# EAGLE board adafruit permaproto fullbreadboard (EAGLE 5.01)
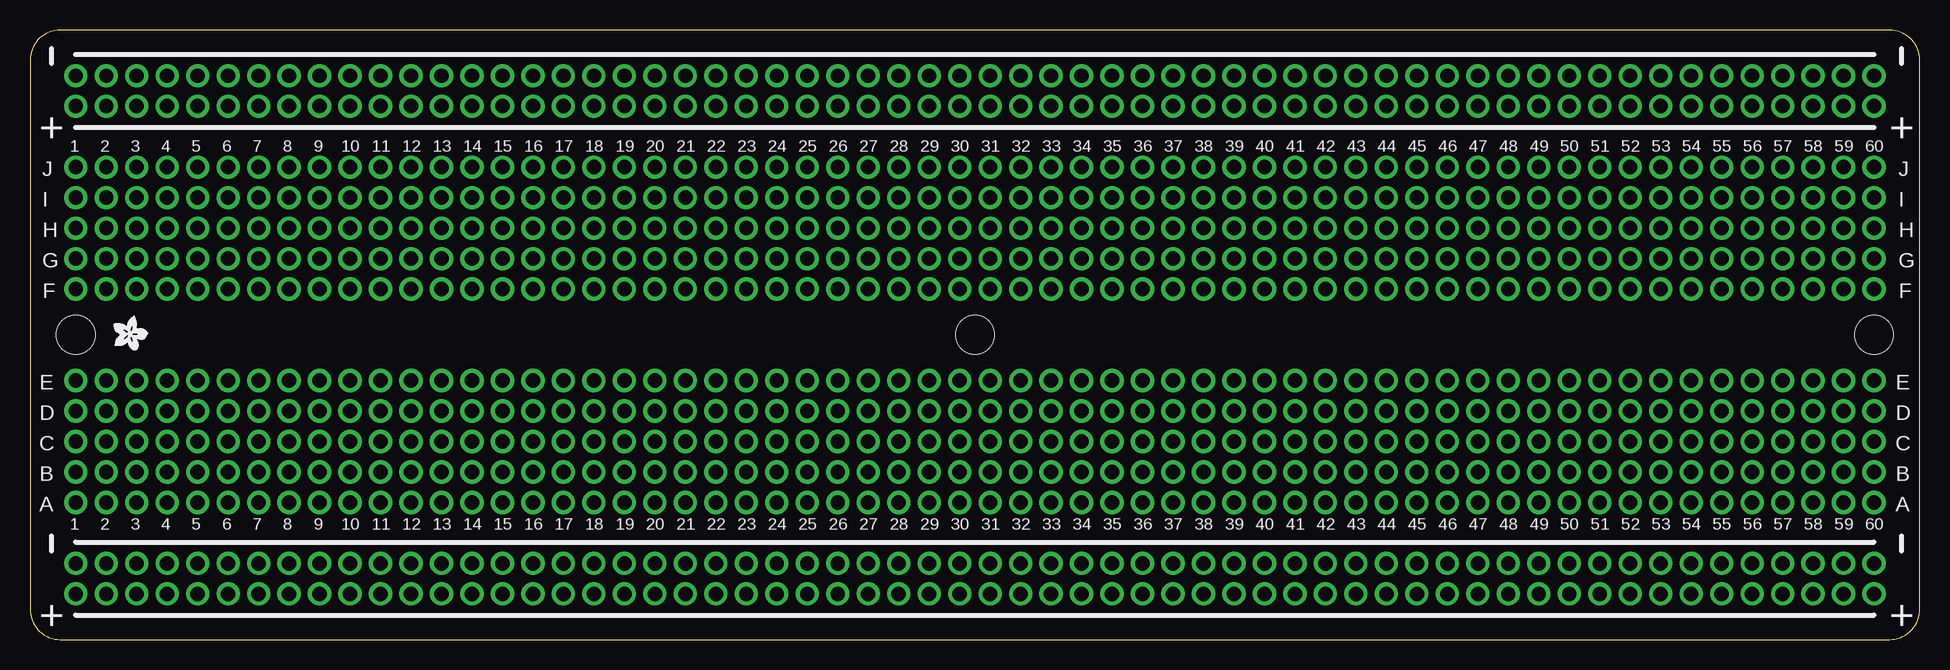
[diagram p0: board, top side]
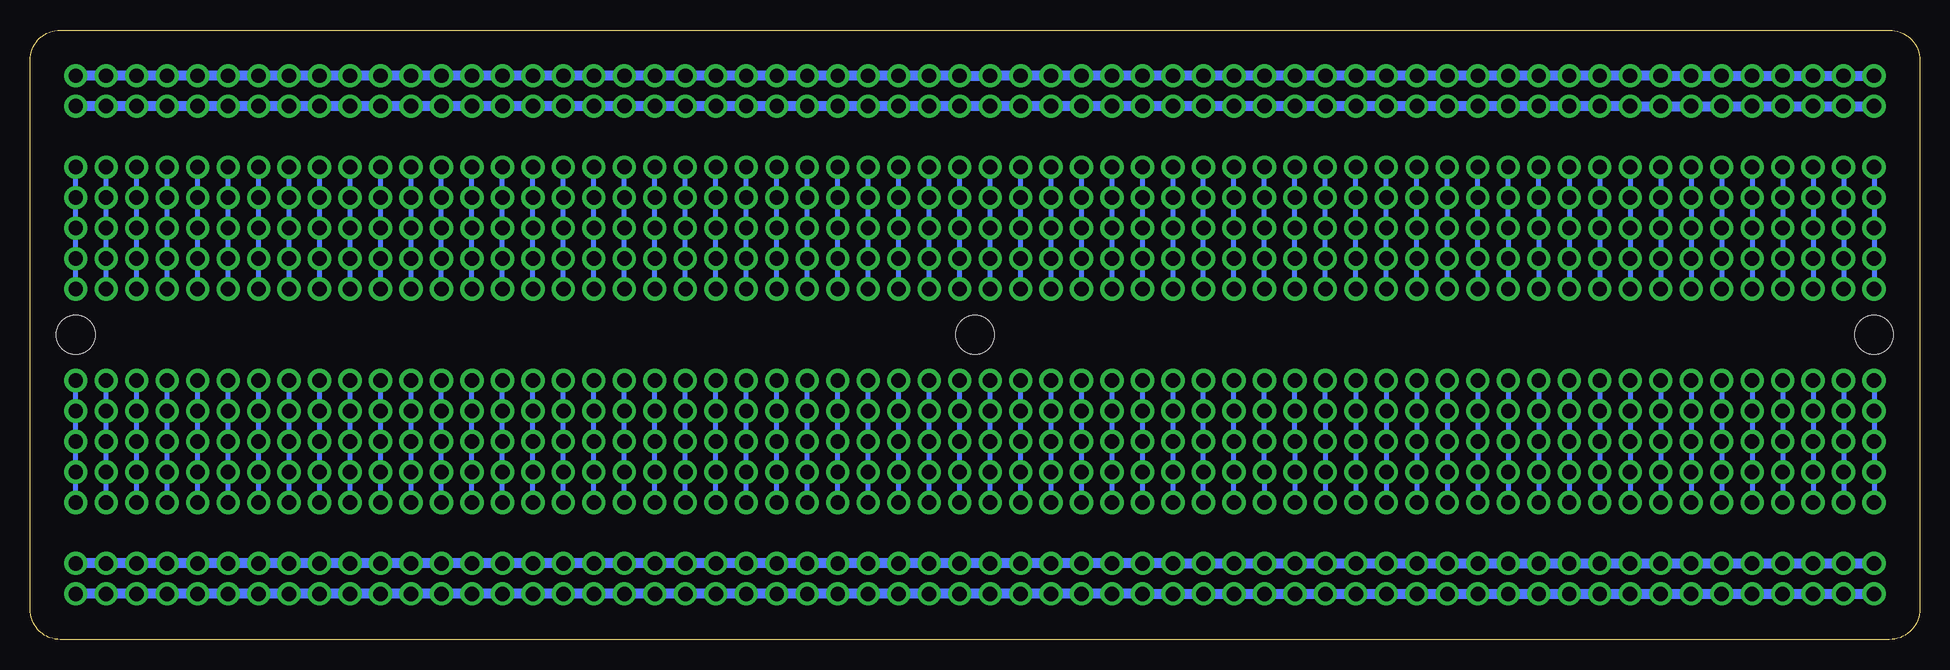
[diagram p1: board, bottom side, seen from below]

Size 157.48 x 50.8 mm. Coordinates in mm from the lower left corner, seen from the top.
Outline: 2.54,50.8 arc90 0,48.26 0,2.54 arc90 2.54,0 154.94,0 arc90 157.48,2.54 157.48,48.26 arc90 154.94,50.8 2.54,50.8
Copper layers (1*16): Top 0.035mm / dielectric 1.5mm / Bottom 0.035mm
Design rules "default": minimum track width 10mil, minimum drill 24mil, track to track 8mil, track to pad 8mil, pad to pad 8mil, via to via 8mil, smd to smd 8mil, copper to edge 40mil, drill to drill 8mil, minimum pad ring 10mil, minimum via ring 8mil, stop-mask expansion 4mil, vias tented up to drill 0mil, thermal gap 10mil
Holes 3.2 mm at 3.81,25.4 153.67,25.4 78.74,25.4

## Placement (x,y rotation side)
U$1  [ADAFRUIT200MIL]  8.38,25.65 270 top

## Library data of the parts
U$1 = adafruit

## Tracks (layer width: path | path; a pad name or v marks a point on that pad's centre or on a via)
N$1  (via drill 1.2 pad 1.93)
  Bottom 0.406: v3.81,21.59 v3.81,19.05 v3.81,16.51 v3.81,13.97 v3.81,11.43
N$2  (via drill 1.2 pad 1.93)
  Bottom 0.406: v6.35,11.43 v6.35,13.97 v6.35,16.51 v6.35,19.05 v6.35,21.59
N$3  (via drill 1.2 pad 1.93)
  Bottom 0.406: v8.89,21.59 v8.89,19.05 v8.89,16.51 v8.89,13.97 v8.89,11.43
N$4  (via drill 1.2 pad 1.93)
  Bottom 0.406: v11.43,11.43 v11.43,13.97 v11.43,16.51 v11.43,19.05 v11.43,21.59
N$5  (via drill 1.2 pad 1.93)
  Bottom 0.406: v13.97,21.59 v13.97,19.05 v13.97,16.51 v13.97,13.97 v13.97,11.43
N$6  (via drill 1.2 pad 1.93)
  Bottom 0.406: v16.51,11.43 v16.51,13.97 v16.51,16.51 v16.51,19.05 v16.51,21.59
N$7  (via drill 1.2 pad 1.93)
  Bottom 0.406: v21.59,11.43 v21.59,13.97 v21.59,16.51 v21.59,19.05 v21.59,21.59
N$8  (via drill 1.2 pad 1.93)
  Bottom 0.406: v19.05,21.59 v19.05,19.05 v19.05,16.51 v19.05,13.97 v19.05,11.43
N$9  (via drill 1.2 pad 1.93)
  Bottom 0.406: v24.13,21.59 v24.13,19.05 v24.13,16.51 v24.13,13.97 v24.13,11.43
N$10  (via drill 1.2 pad 1.93)
  Bottom 0.406: v26.67,21.59 v26.67,19.05 v26.67,16.51 v26.67,13.97 v26.67,11.43
N$11  (via drill 1.2 pad 1.93)
  Bottom 0.406: v29.21,21.59 v29.21,19.05 v29.21,16.51 v29.21,13.97 v29.21,11.43
N$12  (via drill 1.2 pad 1.93)
  Bottom 0.406: v31.75,11.43 v31.75,13.97 v31.75,16.51 v31.75,19.05 v31.75,21.59
N$13  (via drill 1.2 pad 1.93)
  Bottom 0.406: v34.29,21.59 v34.29,19.05 v34.29,16.51 v34.29,13.97 v34.29,11.43
N$14  (via drill 1.2 pad 1.93)
  Bottom 0.406: v36.83,11.43 v36.83,13.97 v36.83,16.51 v36.83,19.05 v36.83,21.59
N$15  (via drill 1.2 pad 1.93)
  Bottom 0.406: v39.37,11.43 v39.37,13.97 v39.37,16.51 | v39.37,19.05 v39.37,16.51 | v39.37,21.59 v39.37,19.05 | v39.37,19.05 v39.37,16.51
N$16  (via drill 1.2 pad 1.93)
  Bottom 0.406: v41.91,21.59 v41.91,19.05 v41.91,16.51 v41.91,13.97 v41.91,11.43
N$17  (via drill 1.2 pad 1.93)
  Bottom 0.406: v46.99,21.59 v46.99,19.05 v46.99,16.51 v46.99,13.97 v46.99,11.43
N$18  (via drill 1.2 pad 1.93)
  Bottom 0.406: v44.45,11.43 v44.45,13.97 v44.45,16.51 v44.45,19.05 v44.45,21.59
N$19  (via drill 1.2 pad 1.93)
  Bottom 0.406: v49.53,21.59 v49.53,19.05 v49.53,16.51 v49.53,13.97 v49.53,11.43
N$20  (via drill 1.2 pad 1.93)
  Bottom 0.406: v52.07,11.43 v52.07,13.97 v52.07,16.51 v52.07,19.05 v52.07,21.59
N$21  (via drill 1.2 pad 1.93)
  Bottom 0.406: v57.15,11.43 v57.15,13.97 v57.15,16.51 v57.15,19.05 v57.15,21.59
N$22  (via drill 1.2 pad 1.93)
  Bottom 0.406: v54.61,21.59 v54.61,19.05 v54.61,16.51 v54.61,13.97 v54.61,11.43
N$23  (via drill 1.2 pad 1.93)
  Bottom 0.406: v59.69,21.59 v59.69,19.05 v59.69,16.51 v59.69,13.97 v59.69,11.43
N$24  (via drill 1.2 pad 1.93)
  Bottom 0.406: v62.23,11.43 v62.23,13.97 v62.23,16.51 v62.23,19.05 v62.23,21.59
N$25  (via drill 1.2 pad 1.93)
  Bottom 0.406: v64.77,21.59 v64.77,19.05 v64.77,16.51 v64.77,13.97 v64.77,11.43
N$26  (via drill 1.2 pad 1.93)
  Bottom 0.406: v67.31,11.43 v67.31,13.97 v67.31,16.51 v67.31,19.05 v67.31,21.59
N$27  (via drill 1.2 pad 1.93)
  Bottom 0.406: v72.39,21.59 v72.39,19.05 v72.39,16.51 v72.39,13.97 v72.39,11.43
N$28  (via drill 1.2 pad 1.93)
  Bottom 0.406: v69.85,11.43 v69.85,13.97 v69.85,16.51 v69.85,19.05 v69.85,21.59
N$29  (via drill 1.2 pad 1.93)
  Bottom 0.406: v74.93,21.59 v74.93,19.05 v74.93,16.51 v74.93,13.97 v74.93,11.43
N$30  (via drill 1.2 pad 1.93)
  Bottom 0.406: v77.47,11.43 v77.47,13.97 v77.47,16.51 v77.47,19.05 v77.47,21.59
N$31  (via drill 1.2 pad 1.93)
  Bottom 0.813: v3.81,6.35 v6.35,6.35 v8.89,6.35 v11.43,6.35 v13.97,6.35 v16.51,6.35 v19.05,6.35 v21.59,6.35 v24.13,6.35 v26.67,6.35 v29.21,6.35 v31.75,6.35 v34.29,6.35 v36.83,6.35 v39.37,6.35 v41.91,6.35 v44.45,6.35 v46.99,6.35 v49.53,6.35 | v52.07,6.35 v49.53,6.35 | v52.07,6.35 v54.61,6.35 v57.15,6.35 v59.69,6.35 v62.23,6.35 v64.77,6.35 v67.31,6.35 | v67.31,6.35 v69.85,6.35 | v69.85,6.35 v72.39,6.35 v74.93,6.35 v77.47,6.35 80.52,6.35 | v67.31,6.35 v69.85,6.35 | v52.07,6.35 v49.53,6.35 | 80.52,6.35 v80.01,6.35 | 80.52,6.35 v82.55,6.35 v85.09,6.35 v87.63,6.35 v90.17,6.35 v92.71,6.35 v95.25,6.35 v97.79,6.35 v100.33,6.35 v102.87,6.35 v105.41,6.35 v107.95,6.35 v110.49,6.35 v113.03,6.35 v115.57,6.35 v118.11,6.35 v120.65,6.35 v123.19,6.35 v125.73,6.35 | v125.73,6.35 v128.27,6.35 | v128.27,6.35 v130.81,6.35 v133.35,6.35 v135.89,6.35 v138.43,6.35 v140.97,6.35 v143.51,6.35 | v143.51,6.35 v146.05,6.35 | v146.05,6.35 v148.59,6.35 v151.13,6.35 v153.67,6.35 | v143.51,6.35 v146.05,6.35 | v125.73,6.35 v128.27,6.35 | 80.52,6.35 80.52,6.1
N$32  (via drill 1.2 pad 1.93)
  Bottom 0.813: v3.81,3.81 v6.35,3.81 v8.89,3.81 v11.43,3.81 v13.97,3.81 v16.51,3.81 v19.05,3.81 v21.59,3.81 v24.13,3.81 v26.67,3.81 v29.21,3.81 v31.75,3.81 v34.29,3.81 v36.83,3.81 v39.37,3.81 v41.91,3.81 v44.45,3.81 v46.99,3.81 v49.53,3.81 | v52.07,3.81 v49.53,3.81 | v52.07,3.81 v54.61,3.81 v57.15,3.81 v59.69,3.81 v62.23,3.81 v64.77,3.81 v67.31,3.81 | v67.31,3.81 v69.85,3.81 | v69.85,3.81 v72.39,3.81 v74.93,3.81 v77.47,3.81 79.76,3.81 | v67.31,3.81 v69.85,3.81 | v52.07,3.81 v49.53,3.81 | v125.73,3.81 v123.19,3.81 v120.65,3.81 v118.11,3.81 v115.57,3.81 v113.03,3.81 v110.49,3.81 v107.95,3.81 v105.41,3.81 v102.87,3.81 v100.33,3.81 v97.79,3.81 v95.25,3.81 v92.71,3.81 v90.17,3.81 v87.63,3.81 v85.09,3.81 v82.55,3.81 v80.01,3.81 79.76,3.81 | v125.73,3.81 v128.27,3.81 | v128.27,3.81 v130.81,3.81 v133.35,3.81 v135.89,3.81 v138.43,3.81 v140.97,3.81 v143.51,3.81 | v143.51,3.81 v146.05,3.81 | v146.05,3.81 v148.59,3.81 v151.13,3.81 v153.67,3.81 | v143.51,3.81 v146.05,3.81 | v125.73,3.81 v128.27,3.81 | 79.76,3.81 79.76,3.56
N$33  (via drill 1.2 pad 1.93)
  Bottom 0.406: v77.47,29.21 v77.47,31.75 v77.47,34.29 v77.47,36.83 v77.47,39.37
N$34  (via drill 1.2 pad 1.93)
  Bottom 0.406: v74.93,39.37 v74.93,36.83 v74.93,34.29 v74.93,31.75 v74.93,29.21
N$35  (via drill 1.2 pad 1.93)
  Bottom 0.406: v72.39,29.21 v72.39,31.75 v72.39,34.29 v72.39,36.83 v72.39,39.37
N$36  (via drill 1.2 pad 1.93)
  Bottom 0.406: v69.85,39.37 v69.85,36.83 v69.85,34.29 v69.85,31.75 v69.85,29.21
N$37  (via drill 1.2 pad 1.93)
  Bottom 0.406: v67.31,29.21 v67.31,31.75 v67.31,34.29 v67.31,36.83 v67.31,39.37
N$38  (via drill 1.2 pad 1.93)
  Bottom 0.406: v64.77,39.37 v64.77,36.83 v64.77,34.29 v64.77,31.75 v64.77,29.21
N$39  (via drill 1.2 pad 1.93)
  Bottom 0.406: v59.69,39.37 v59.69,36.83 v59.69,34.29 v59.69,31.75 v59.69,29.21
N$40  (via drill 1.2 pad 1.93)
  Bottom 0.406: v62.23,29.21 v62.23,31.75 v62.23,34.29 v62.23,36.83 v62.23,39.37
N$41  (via drill 1.2 pad 1.93)
  Bottom 0.406: v57.15,29.21 v57.15,31.75 v57.15,34.29 v57.15,36.83 v57.15,39.37
N$42  (via drill 1.2 pad 1.93)
  Bottom 0.406: v54.61,29.21 v54.61,31.75 v54.61,34.29 v54.61,36.83 v54.61,39.37
N$43  (via drill 1.2 pad 1.93)
  Bottom 0.406: v52.07,29.21 v52.07,31.75 v52.07,34.29 v52.07,36.83 v52.07,39.37
N$44  (via drill 1.2 pad 1.93)
  Bottom 0.406: v49.53,39.37 v49.53,36.83 v49.53,34.29 v49.53,31.75 v49.53,29.21
N$45  (via drill 1.2 pad 1.93)
  Bottom 0.406: v46.99,29.21 v46.99,31.75 v46.99,34.29 v46.99,36.83 v46.99,39.37
N$46  (via drill 1.2 pad 1.93)
  Bottom 0.406: v44.45,39.37 v44.45,36.83 v44.45,34.29 v44.45,31.75 v44.45,29.21
N$47  (via drill 1.2 pad 1.93)
  Bottom 0.406: v41.91,39.37 v41.91,36.83 v41.91,34.29 | v41.91,31.75 v41.91,34.29 | v41.91,29.21 v41.91,31.75 | v41.91,31.75 v41.91,34.29
N$48  (via drill 1.2 pad 1.93)
  Bottom 0.406: v39.37,29.21 v39.37,31.75 v39.37,34.29 v39.37,36.83 v39.37,39.37
N$49  (via drill 1.2 pad 1.93)
  Bottom 0.406: v34.29,29.21 v34.29,31.75 v34.29,34.29 v34.29,36.83 v34.29,39.37
N$50  (via drill 1.2 pad 1.93)
  Bottom 0.406: v36.83,39.37 v36.83,36.83 v36.83,34.29 v36.83,31.75 v36.83,29.21
N$51  (via drill 1.2 pad 1.93)
  Bottom 0.406: v31.75,29.21 v31.75,31.75 v31.75,34.29 v31.75,36.83 v31.75,39.37
N$52  (via drill 1.2 pad 1.93)
  Bottom 0.406: v29.21,39.37 v29.21,36.83 v29.21,34.29 v29.21,31.75 v29.21,29.21
N$53  (via drill 1.2 pad 1.93)
  Bottom 0.406: v24.13,39.37 v24.13,36.83 v24.13,34.29 v24.13,31.75 v24.13,29.21
N$54  (via drill 1.2 pad 1.93)
  Bottom 0.406: v26.67,29.21 v26.67,31.75 v26.67,34.29 v26.67,36.83 v26.67,39.37
N$55  (via drill 1.2 pad 1.93)
  Bottom 0.406: v21.59,29.21 v21.59,31.75 v21.59,34.29 v21.59,36.83 v21.59,39.37
N$56  (via drill 1.2 pad 1.93)
  Bottom 0.406: v19.05,39.37 v19.05,36.83 v19.05,34.29 v19.05,31.75 v19.05,29.21
N$57  (via drill 1.2 pad 1.93)
  Bottom 0.406: v16.51,29.21 v16.51,31.75 v16.51,34.29 v16.51,36.83 v16.51,39.37
N$58  (via drill 1.2 pad 1.93)
  Bottom 0.406: v13.97,39.37 v13.97,36.83 v13.97,34.29 v13.97,31.75 v13.97,29.21
N$59  (via drill 1.2 pad 1.93)
  Bottom 0.406: v8.89,29.21 v8.89,31.75 v8.89,34.29 v8.89,36.83 v8.89,39.37
N$60  (via drill 1.2 pad 1.93)
  Bottom 0.406: v11.43,39.37 v11.43,36.83 v11.43,34.29 v11.43,31.75 v11.43,29.21
N$61  (via drill 1.2 pad 1.93)
  Bottom 0.406: v6.35,29.21 v6.35,31.75 v6.35,34.29 v6.35,36.83 v6.35,39.37
N$62  (via drill 1.2 pad 1.93)
  Bottom 0.406: v3.81,39.37 v3.81,36.83 v3.81,34.29 v3.81,31.75 v3.81,29.21
N$63  (via drill 1.2 pad 1.93)
  Bottom 0.813: v31.75,44.45 v34.29,44.45 v36.83,44.45 v39.37,44.45 v41.91,44.45 v44.45,44.45 v46.99,44.45 v49.53,44.45 v52.07,44.45 v54.61,44.45 v57.15,44.45 v59.69,44.45 v62.23,44.45 v64.77,44.45 v67.31,44.45 v69.85,44.45 v72.39,44.45 v74.93,44.45 v77.47,44.45 v80.01,44.45 v82.55,44.45 v85.09,44.45 v87.63,44.45 | v29.21,44.45 v31.75,44.45 | v29.21,44.45 v26.67,44.45 v24.13,44.45 v21.59,44.45 v19.05,44.45 v16.51,44.45 v13.97,44.45 | v13.97,44.45 v11.43,44.45 | v11.43,44.45 v8.89,44.45 v6.35,44.45 v3.81,44.45 | v13.97,44.45 v11.43,44.45 | v29.21,44.45 v31.75,44.45 | v153.67,44.45 v151.13,44.45 v148.59,44.45 v146.05,44.45 v143.51,44.45 v140.97,44.45 v138.43,44.45 v135.89,44.45 v133.35,44.45 v130.81,44.45 v128.27,44.45 v125.73,44.45 v123.19,44.45 v120.65,44.45 v118.11,44.45 v115.57,44.45 v113.03,44.45 v110.49,44.45 v107.95,44.45 | v105.41,44.45 v107.95,44.45 | v105.41,44.45 v102.87,44.45 v100.33,44.45 v97.79,44.45 v95.25,44.45 v92.71,44.45 v90.17,44.45 | v87.63,44.45 v90.17,44.45 | v87.63,44.45 v90.17,44.45 | v105.41,44.45 v107.95,44.45
N$64  (via drill 1.2 pad 1.93)
  Bottom 0.813: v31.75,46.99 v34.29,46.99 v36.83,46.99 v39.37,46.99 v41.91,46.99 v44.45,46.99 v46.99,46.99 v49.53,46.99 v52.07,46.99 v54.61,46.99 v57.15,46.99 v59.69,46.99 v62.23,46.99 v64.77,46.99 v67.31,46.99 v69.85,46.99 v72.39,46.99 v74.93,46.99 v77.47,46.99 v80.01,46.99 v82.55,46.99 v85.09,46.99 v87.63,46.99 | v29.21,46.99 v31.75,46.99 | v29.21,46.99 v26.67,46.99 v24.13,46.99 v21.59,46.99 v19.05,46.99 v16.51,46.99 v13.97,46.99 | v13.97,46.99 v11.43,46.99 | v11.43,46.99 v8.89,46.99 v6.35,46.99 v3.81,46.99 | v13.97,46.99 v11.43,46.99 | v29.21,46.99 v31.75,46.99 | v153.67,46.99 v151.13,46.99 v148.59,46.99 v146.05,46.99 v143.51,46.99 v140.97,46.99 v138.43,46.99 v135.89,46.99 v133.35,46.99 v130.81,46.99 v128.27,46.99 v125.73,46.99 v123.19,46.99 v120.65,46.99 v118.11,46.99 v115.57,46.99 v113.03,46.99 v110.49,46.99 v107.95,46.99 | v105.41,46.99 v107.95,46.99 | v105.41,46.99 v102.87,46.99 v100.33,46.99 v97.79,46.99 v95.25,46.99 v92.71,46.99 v90.17,46.99 | v87.63,46.99 v90.17,46.99 | v87.63,46.99 v90.17,46.99 | v105.41,46.99 v107.95,46.99
N$65  (via drill 1.2 pad 1.93)
  Bottom 0.406: v80.01,21.59 v80.01,19.05 v80.01,16.51 v80.01,13.97 v80.01,11.43
N$66  (via drill 1.2 pad 1.93)
  Bottom 0.406: v82.55,11.43 v82.55,13.97 v82.55,16.51 v82.55,19.05 v82.55,21.59
N$67  (via drill 1.2 pad 1.93)
  Bottom 0.406: v85.09,21.59 v85.09,19.05 v85.09,16.51 v85.09,13.97 v85.09,11.43
N$68  (via drill 1.2 pad 1.93)
  Bottom 0.406: v87.63,11.43 v87.63,13.97 v87.63,16.51 v87.63,19.05 v87.63,21.59
N$69  (via drill 1.2 pad 1.93)
  Bottom 0.406: v90.17,21.59 v90.17,19.05 v90.17,16.51 v90.17,13.97 v90.17,11.43
N$70  (via drill 1.2 pad 1.93)
  Bottom 0.406: v92.71,11.43 v92.71,13.97 v92.71,16.51 v92.71,19.05 v92.71,21.59
N$71  (via drill 1.2 pad 1.93)
  Bottom 0.406: v97.79,11.43 v97.79,13.97 v97.79,16.51 v97.79,19.05 v97.79,21.59
N$72  (via drill 1.2 pad 1.93)
  Bottom 0.406: v95.25,21.59 v95.25,19.05 v95.25,16.51 v95.25,13.97 v95.25,11.43
N$73  (via drill 1.2 pad 1.93)
  Bottom 0.406: v100.33,21.59 v100.33,19.05 v100.33,16.51 v100.33,13.97 v100.33,11.43
N$74  (via drill 1.2 pad 1.93)
  Bottom 0.406: v102.87,21.59 v102.87,19.05 v102.87,16.51 v102.87,13.97 v102.87,11.43
N$75  (via drill 1.2 pad 1.93)
  Bottom 0.406: v105.41,21.59 v105.41,19.05 v105.41,16.51 v105.41,13.97 v105.41,11.43
N$76  (via drill 1.2 pad 1.93)
  Bottom 0.406: v107.95,11.43 v107.95,13.97 v107.95,16.51 v107.95,19.05 v107.95,21.59
N$77  (via drill 1.2 pad 1.93)
  Bottom 0.406: v110.49,21.59 v110.49,19.05 v110.49,16.51 v110.49,13.97 v110.49,11.43
N$78  (via drill 1.2 pad 1.93)
  Bottom 0.406: v113.03,11.43 v113.03,13.97 v113.03,16.51 v113.03,19.05 v113.03,21.59
N$79  (via drill 1.2 pad 1.93)
  Bottom 0.406: v115.57,11.43 v115.57,13.97 v115.57,16.51 | v115.57,16.51 v115.57,19.05 | v115.57,19.05 v115.57,21.59 | v115.57,16.51 v115.57,19.05
N$80  (via drill 1.2 pad 1.93)
  Bottom 0.406: v118.11,21.59 v118.11,19.05 v118.11,16.51 v118.11,13.97 v118.11,11.43
N$81  (via drill 1.2 pad 1.93)
  Bottom 0.406: v123.19,21.59 v123.19,19.05 v123.19,16.51 v123.19,13.97 v123.19,11.43
N$82  (via drill 1.2 pad 1.93)
  Bottom 0.406: v120.65,11.43 v120.65,13.97 v120.65,16.51 v120.65,19.05 v120.65,21.59
N$83  (via drill 1.2 pad 1.93)
  Bottom 0.406: v125.73,21.59 v125.73,19.05 v125.73,16.51 v125.73,13.97 v125.73,11.43
N$84  (via drill 1.2 pad 1.93)
  Bottom 0.406: v128.27,11.43 v128.27,13.97 v128.27,16.51 v128.27,19.05 v128.27,21.59
N$85  (via drill 1.2 pad 1.93)
  Bottom 0.406: v133.35,11.43 v133.35,13.97 v133.35,16.51 v133.35,19.05 v133.35,21.59
N$86  (via drill 1.2 pad 1.93)
  Bottom 0.406: v130.81,21.59 v130.81,19.05 v130.81,16.51 v130.81,13.97 v130.81,11.43
N$87  (via drill 1.2 pad 1.93)
  Bottom 0.406: v135.89,21.59 v135.89,19.05 v135.89,16.51 v135.89,13.97 v135.89,11.43
N$88  (via drill 1.2 pad 1.93)
  Bottom 0.406: v138.43,11.43 v138.43,13.97 v138.43,16.51 v138.43,19.05 v138.43,21.59
N$89  (via drill 1.2 pad 1.93)
  Bottom 0.406: v140.97,21.59 v140.97,19.05 v140.97,16.51 v140.97,13.97 v140.97,11.43
N$90  (via drill 1.2 pad 1.93)
  Bottom 0.406: v143.51,11.43 v143.51,13.97 v143.51,16.51 v143.51,19.05 v143.51,21.59
N$91  (via drill 1.2 pad 1.93)
  Bottom 0.406: v148.59,21.59 v148.59,19.05 v148.59,16.51 v148.59,13.97 v148.59,11.43
N$92  (via drill 1.2 pad 1.93)
  Bottom 0.406: v146.05,11.43 v146.05,13.97 v146.05,16.51 v146.05,19.05 v146.05,21.59
N$93  (via drill 1.2 pad 1.93)
  Bottom 0.406: v151.13,21.59 v151.13,19.05 v151.13,16.51 v151.13,13.97 v151.13,11.43
N$94  (via drill 1.2 pad 1.93)
  Bottom 0.406: v153.67,11.43 v153.67,13.97 v153.67,16.51 v153.67,19.05 v153.67,21.59
N$97  (via drill 1.2 pad 1.93)
  Bottom 0.406: v153.67,29.21 v153.67,31.75 v153.67,34.29 v153.67,36.83 v153.67,39.37
N$98  (via drill 1.2 pad 1.93)
  Bottom 0.406: v151.13,39.37 v151.13,36.83 v151.13,34.29 v151.13,31.75 v151.13,29.21
N$99  (via drill 1.2 pad 1.93)
  Bottom 0.406: v148.59,29.21 v148.59,31.75 v148.59,34.29 v148.59,36.83 v148.59,39.37
N$100  (via drill 1.2 pad 1.93)
  Bottom 0.406: v146.05,39.37 v146.05,36.83 v146.05,34.29 v146.05,31.75 v146.05,29.21
N$101  (via drill 1.2 pad 1.93)
  Bottom 0.406: v143.51,29.21 v143.51,31.75 v143.51,34.29 v143.51,36.83 v143.51,39.37
N$102  (via drill 1.2 pad 1.93)
  Bottom 0.406: v140.97,39.37 v140.97,36.83 v140.97,34.29 v140.97,31.75 v140.97,29.21
N$103  (via drill 1.2 pad 1.93)
  Bottom 0.406: v135.89,39.37 v135.89,36.83 v135.89,34.29 v135.89,31.75 v135.89,29.21
N$104  (via drill 1.2 pad 1.93)
  Bottom 0.406: v138.43,29.21 v138.43,31.75 v138.43,34.29 v138.43,36.83 v138.43,39.37
N$105  (via drill 1.2 pad 1.93)
  Bottom 0.406: v133.35,29.21 v133.35,31.75 v133.35,34.29 v133.35,36.83 v133.35,39.37
N$106  (via drill 1.2 pad 1.93)
  Bottom 0.406: v130.81,29.21 v130.81,31.75 v130.81,34.29 v130.81,36.83 v130.81,39.37
N$107  (via drill 1.2 pad 1.93)
  Bottom 0.406: v128.27,29.21 v128.27,31.75 v128.27,34.29 v128.27,36.83 v128.27,39.37
N$108  (via drill 1.2 pad 1.93)
  Bottom 0.406: v125.73,39.37 v125.73,36.83 v125.73,34.29 v125.73,31.75 v125.73,29.21
N$109  (via drill 1.2 pad 1.93)
  Bottom 0.406: v123.19,29.21 v123.19,31.75 v123.19,34.29 v123.19,36.83 v123.19,39.37
N$110  (via drill 1.2 pad 1.93)
  Bottom 0.406: v120.65,39.37 v120.65,36.83 v120.65,34.29 v120.65,31.75 v120.65,29.21
N$111  (via drill 1.2 pad 1.93)
  Bottom 0.406: v118.11,39.37 v118.11,36.83 v118.11,34.29 | v118.11,31.75 v118.11,34.29 | v118.11,29.21 v118.11,31.75 | v118.11,31.75 v118.11,34.29
N$112  (via drill 1.2 pad 1.93)
  Bottom 0.406: v115.57,29.21 v115.57,31.75 v115.57,34.29 v115.57,36.83 v115.57,39.37
N$113  (via drill 1.2 pad 1.93)
  Bottom 0.406: v110.49,29.21 v110.49,31.75 v110.49,34.29 v110.49,36.83 v110.49,39.37
N$114  (via drill 1.2 pad 1.93)
  Bottom 0.406: v113.03,39.37 v113.03,36.83 v113.03,34.29 v113.03,31.75 v113.03,29.21
N$115  (via drill 1.2 pad 1.93)
  Bottom 0.406: v107.95,29.21 v107.95,31.75 v107.95,34.29 v107.95,36.83 v107.95,39.37
N$116  (via drill 1.2 pad 1.93)
  Bottom 0.406: v105.41,39.37 v105.41,36.83 v105.41,34.29 v105.41,31.75 v105.41,29.21
N$117  (via drill 1.2 pad 1.93)
  Bottom 0.406: v100.33,39.37 v100.33,36.83 v100.33,34.29 v100.33,31.75 v100.33,29.21
N$118  (via drill 1.2 pad 1.93)
  Bottom 0.406: v102.87,29.21 v102.87,31.75 v102.87,34.29 v102.87,36.83 v102.87,39.37
N$119  (via drill 1.2 pad 1.93)
  Bottom 0.406: v97.79,29.21 v97.79,31.75 v97.79,34.29 v97.79,36.83 v97.79,39.37
N$120  (via drill 1.2 pad 1.93)
  Bottom 0.406: v95.25,39.37 v95.25,36.83 v95.25,34.29 v95.25,31.75 v95.25,29.21
N$121  (via drill 1.2 pad 1.93)
  Bottom 0.406: v92.71,29.21 v92.71,31.75 v92.71,34.29 v92.71,36.83 v92.71,39.37
N$122  (via drill 1.2 pad 1.93)
  Bottom 0.406: v90.17,39.37 v90.17,36.83 v90.17,34.29 v90.17,31.75 v90.17,29.21
N$123  (via drill 1.2 pad 1.93)
  Bottom 0.406: v85.09,29.21 v85.09,31.75 v85.09,34.29 v85.09,36.83 v85.09,39.37
N$124  (via drill 1.2 pad 1.93)
  Bottom 0.406: v87.63,39.37 v87.63,36.83 v87.63,34.29 v87.63,31.75 v87.63,29.21
N$125  (via drill 1.2 pad 1.93)
  Bottom 0.406: v82.55,29.21 v82.55,31.75 v82.55,34.29 v82.55,36.83 v82.55,39.37
N$126  (via drill 1.2 pad 1.93)
  Bottom 0.406: v80.01,39.37 v80.01,36.83 v80.01,34.29 v80.01,31.75 v80.01,29.21

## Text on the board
tPlace: 1 | 2 | 3 | 4 | 5 | 6 | 7 | 8 | 9 | 10 | 11 | 12 | 13 | 14 | 15 | 16 | 17 | 18 | 19 | 20 | 21 | 22 | 23 | 24 | 25 | 26 | 27 | 28 | 29 | 30 | 31 | 32 | 33 | 34 | 35 | 36 | 37 | 38 | 39 | 40 | 41 | 42 | 43 | 44 | 45 | 46 | 47 | 48 | 49 | 50 | 51 | 52 | 53 | 54 | 55 | 56 | 57 | 58 | 59 | 60 | J | J | I | I | H | H | G | G | F | F | E | E | D | D | C | C | B | B | A | A | 1 | 2 | 3 | 4 | 5 | 6 | 7 | 8 | 9 | 10 | 11 | 12 | 13 | 14 | 15 | 16 | 17 | 18 | 19 | 20 | 21 | 22 | 23 | 24 | 25 | 26 | 27 | 28 | 29 | 30 | 31 | 32 | 33 | 34 | 35 | 36 | 37 | 38 | 39 | 40 | 41 | 42 | 43 | 44 | 45 | 46 | 47 | 48 | 49 | 50 | 51 | 52 | 53 | 54 | 55 | 56 | 57 | 58 | 59 | 60
tDocu: Adafruit Perma-Proto Full Sized Breadboard
tPlaceRed: + | + | + | +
